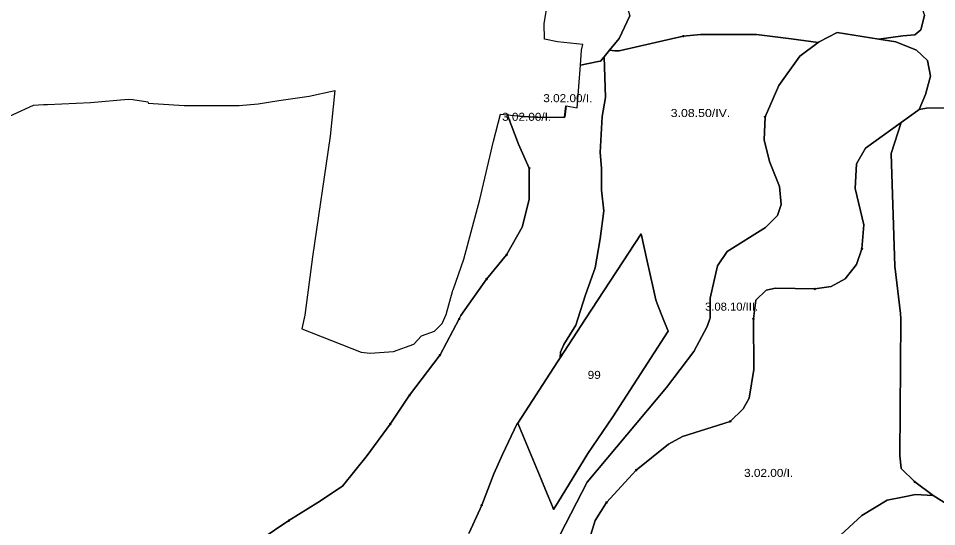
# Model space of a CAD drawing. Extents: x -650455 to -642254, y -1075222 to -1066610.
# Drawn here: x -646541 to -645394, y -1068260 to -1067624 of the extents above; entities that cross this region are included whole.
import ezdxf
from ezdxf.enums import TextEntityAlignment as Align

# ---------------------------------------------------------------- set-up
doc = ezdxf.new("R2010")
doc.units = 0
doc.header["$LTSCALE"] = 4
doc.header["$PDMODE"] = 32
doc.header["$PDSIZE"] = 2
for name, color, linetype, lineweight in [('1', 7, 'Continuous', 25), ('11', 7, 'Continuous', 13), ('12', 7, 'Continuous', 13), ('13', 7, 'Continuous', 13), ('14', 7, 'Continuous', 13)]:
    doc.layers.add(name, color=color, linetype=linetype, lineweight=lineweight)
doc.layers.add('2', color=7, linetype='Continuous')

msp = doc.modelspace()

# ---------------------------------------------------------------- linework, layer by layer
at = {"layer": '1'}
for points in [[(-645802.687, -1067663.876), (-645809.375, -1067672.25), (-645814.125, -1067677.751), (-645816.835, -1067678.312), (-645839.087, -1067682.923), (-645837.619, -1067663.994), (-645836.027, -1067656.984), (-645867.933, -1067653.635), (-645883.859, -1067650.419), (-645884.5, -1067630.76), (-645873.323, -1067563.051), (-645890.073, -1067549.417), (-645890.669, -1067543.411), (-645885.177, -1067516.651), (-645845.49, -1067511.661), (-645830.352, -1067509.283), (-645829.312, -1067510.75), (-645814.25, -1067527.251), (-645796.188, -1067560.375), (-645788.625, -1067583), (-645788.254, -1067585.104), (-645788.25, -1067585.125), (-645777.5, -1067621.251), (-645790.813, -1067649.501)], [(-645857.007, -1067733.671), (-645858.438, -1067747.75), (-645858.794, -1067747.75), (-645857.238, -1067733.631)], [(-645892.381, -1067747.75), (-645895.062, -1067747.75), (-645912.313, -1067746.751), (-645917.164, -1067746.206)], [(-645917.313, -1068130.126), (-645867.687, -1068053.501), (-645864.5, -1068048.626), (-645832.678, -1068000), (-645763.063, -1067893.626), (-645755.688, -1067927.876), (-645748.438, -1067961.001), (-645744.938, -1067976.25), (-645742.687, -1067982.125), (-645735.605, -1068000), (-645729.568, -1068015.238), (-645729.57, -1068015.25), (-645798.69, -1068122.171), (-645829.66, -1068168.341), (-645867.779, -1068230.191), (-645872.671, -1068238), (-645874.15, -1068234.441), (-645882.74, -1068213.72), (-645888.25, -1068200.251)]]:
    msp.add_lwpolyline(points, close=True, dxfattribs=at)
for points in [[(-645416.812, -1067598), (-645409.312, -1067620.625), (-645413.813, -1067638.626), (-645421.375, -1067644.751), (-645436.375, -1067646.251), (-645466.563, -1067650.126)], [(-645466.563, -1067650.126), (-645518.5, -1067642.001), (-645541, -1067653.501), (-645542.25, -1067654.375), (-645576, -1067649.875), (-645619.125, -1067644.625), (-645689.063, -1067644.625), (-645710.625, -1067646.5), (-645790.875, -1067664.75), (-645796.062, -1067664.75), (-645802.687, -1067663.876), (-645790.813, -1067649.501), (-645777.5, -1067621.251)], [(-645149.54, -1067732.723), (-645175, -1067727.5), (-645192.189, -1067725.08), (-645192.187, -1067725.126), (-645210.5, -1067722.501), (-645305, -1067735.501), (-645407, -1067736.5), (-645416, -1067738.001), (-645408, -1067719.5), (-645402, -1067696.5), (-645405.5, -1067677.001), (-645419.5, -1067664), (-645445, -1067653.501), (-645466.563, -1067650.126), (-645436.375, -1067646.251), (-645421.375, -1067644.751), (-645413.813, -1067638.626), (-645409.312, -1067620.625)], [(-645864.5, -1068269.501), (-645830.5, -1068204.001), (-645731.5, -1068085.5), (-645697.5, -1068040.5), (-645681, -1068009.501), (-645677.381, -1068000), (-645677, -1067999), (-645677, -1067974.001), (-645668, -1067933.501), (-645656, -1067915.5), (-645608, -1067885.5), (-645593, -1067870.5), (-645588.5, -1067857.001), (-645590.5, -1067834.5), (-645603, -1067803.001), (-645609.5, -1067776.001), (-645608.5, -1067747.501), (-645591.5, -1067708), (-645565, -1067671.5), (-645542.25, -1067654.375), (-645541, -1067653.501), (-645518.5, -1067642.001), (-645466.563, -1067650.126)], [(-645814.437, -1067791.875), (-645812.125, -1067746.751), (-645807.625, -1067723.125), (-645809.375, -1067672.25), (-645802.687, -1067663.876), (-645796.062, -1067664.75), (-645790.875, -1067664.75), (-645710.625, -1067646.5), (-645689.063, -1067644.625), (-645619.125, -1067644.625), (-645576, -1067649.875), (-645542.25, -1067654.375)], [(-645542.25, -1067654.375), (-645565, -1067671.5), (-645591.5, -1067708), (-645608.5, -1067747.501), (-645609.5, -1067776.001), (-645603, -1067803.001), (-645590.5, -1067834.5), (-645588.5, -1067857.001), (-645593, -1067870.5), (-645608, -1067885.5), (-645656, -1067915.5), (-645668, -1067933.501), (-645677, -1067974.001), (-645677, -1067999), (-645677.381, -1068000), (-645681, -1068009.501), (-645697.5, -1068040.5), (-645731.5, -1068085.5), (-645830.5, -1068204.001), (-645864.5, -1068269.501)], [(-645466.563, -1067650.126), (-645445, -1067653.501), (-645419.5, -1067664), (-645405.5, -1067677.001), (-645402, -1067696.5), (-645408, -1067719.5), (-645416, -1067738.001), (-645417.864, -1067739.367), (-645417.875, -1067739.375), (-645438.5, -1067754.501), (-645483, -1067786.501), (-645494.5, -1067806), (-645496, -1067837), (-645485, -1067882.5), (-645487.5, -1067912.501), (-645494.5, -1067932), (-645508.5, -1067950.001), (-645526, -1067959.5), (-645546.5, -1067962.5), (-645595.5, -1067961.501), (-645607, -1067964), (-645620, -1067976.5), (-645623, -1068000), (-645622.5, -1068063.001), (-645628.5, -1068099.001), (-645636, -1068112.5), (-645652, -1068128.001), (-645711.5, -1068147.001), (-645729, -1068156.501), (-645769.5, -1068189.001), (-645806.5, -1068229.501), (-645820.5, -1068252.001), (-645833, -1068292.501)], [(-645858.438, -1067747.75), (-645857.007, -1067733.671), (-645843.207, -1067736.051), (-645839.087, -1067682.923), (-645816.835, -1067678.312), (-645814.125, -1067677.751), (-645809.375, -1067672.25), (-645807.625, -1067723.125), (-645812.125, -1067746.751), (-645814.437, -1067791.875), (-645812.938, -1067811.625), (-645812.938, -1067839.001), (-645809.875, -1067864.875), (-645814.437, -1067899.875), (-645820.5, -1067936.251), (-645832.688, -1067969.751), (-645842.34, -1068000), (-645844.812, -1068007.75), (-645860, -1068032), (-645863.813, -1068041.625), (-645864.5, -1068048.626)], [(-646334.1, -1067733.4), (-646265.3, -1067733), (-646241.8, -1067731.001), (-646215.6, -1067727.001), (-646177.7, -1067721.601), (-646147.4, -1067714.8), (-646145.864, -1067714.305), (-646151.5, -1067771.46), (-646173.854, -1067922.41), (-646183.168, -1067995.4), (-646186.894, -1068012.483), (-646113.002, -1068041.368), (-646101.826, -1068042.921), (-646072.642, -1068040.746), (-646047.184, -1068031.428), (-646037.588, -1068021.117), (-646021.3, -1068015.101), (-646011.9, -1068005.551), (-646007, -1067994.3), (-645998.8, -1067965.701), (-645998.424, -1067963.832), (-645998.13, -1067963.409), (-645984.78, -1067925.205), (-645964.91, -1067850.661), (-645947.524, -1067777.671), (-645939.12, -1067744.039), (-645930.106, -1067744.937), (-645930.062, -1067745.376), (-645916.5, -1067781.5), (-645902.938, -1067811.625), (-645902.938, -1067850.75), (-645912, -1067885.375), (-645931.312, -1067920.001), (-645956.375, -1067950.25), (-645988.312, -1067995.75), (-645990.562, -1068000), (-646014.375, -1068045), (-646052.625, -1068095.375), (-646076.688, -1068131.501), (-646105.312, -1068170.75)], [(-646573.28, -1067755.921), (-646522.089, -1067732.688), (-646509.898, -1067731.813), (-646504.716, -1067732.104), (-646450.811, -1067729.365), (-646404.167, -1067725.184), (-646398.3, -1067725.601), (-646379.3, -1067728.5), (-646379.05, -1067730.4), (-646334.1, -1067733.4)], [(-645369.687, -1068238.75), (-645398.687, -1068220.501), (-645421.625, -1068203.625), (-645438.375, -1068186.876), (-645438.625, -1068186.5), (-645440, -1068171.001), (-645439, -1068001.001), (-645439.063, -1068000), (-645439.5, -1067993.001), (-645446.5, -1067934), (-645451, -1067793), (-645438.5, -1067754.501), (-645417.875, -1067739.375), (-645417.864, -1067739.367), (-645416, -1067738.001), (-645407, -1067736.5), (-645305, -1067735.501)], [(-646239.25, -1068276.126), (-646203.125, -1068252.001), (-646167, -1068229.375), (-646136.312, -1068209.001), (-646105.312, -1068170.75), (-646076.688, -1068131.501), (-646052.625, -1068095.375), (-646014.375, -1068045), (-645990.562, -1068000), (-645988.312, -1067995.75), (-645956.375, -1067950.25), (-645931.312, -1067920.001), (-645912, -1067885.375), (-645902.938, -1067850.75), (-645902.938, -1067811.625), (-645916.5, -1067781.5), (-645930.062, -1067745.376), (-645930.106, -1067744.937), (-645917.73, -1067746.171), (-645917.164, -1067746.206), (-645912.313, -1067746.751), (-645895.062, -1067747.75), (-645892.381, -1067747.75), (-645892.22, -1067747.761), (-645858.82, -1067747.99), (-645858.794, -1067747.75), (-645858.438, -1067747.75)], [(-645494.5, -1067806), (-645483, -1067786.501), (-645438.5, -1067754.501), (-645451, -1067793), (-645446.5, -1067934), (-645439.5, -1067993.001), (-645439.063, -1068000), (-645439, -1068001.001), (-645440, -1068171.001), (-645438.625, -1068186.5), (-645438.375, -1068186.876), (-645421.625, -1068203.625), (-645398.687, -1068220.501)], [(-645977.937, -1068267.25), (-645962.438, -1068232.625), (-645947.25, -1068193.626), (-645936.625, -1068169.376), (-645918.062, -1068130.501), (-645917.313, -1068130.126), (-645888.25, -1068200.251), (-645882.74, -1068213.72), (-645874.15, -1068234.441), (-645872.671, -1068238), (-645867.779, -1068230.191), (-645829.66, -1068168.341), (-645798.69, -1068122.171), (-645729.57, -1068015.25), (-645729.568, -1068015.238), (-645735.605, -1068000), (-645742.687, -1067982.125), (-645744.938, -1067976.25), (-645748.438, -1067961.001), (-645755.688, -1067927.876), (-645763.063, -1067893.626), (-645832.678, -1068000), (-645864.5, -1068048.626), (-645863.813, -1068041.625), (-645860, -1068032), (-645844.812, -1068007.75), (-645842.34, -1068000), (-645832.688, -1067969.751), (-645820.5, -1067936.251), (-645814.437, -1067899.875), (-645809.875, -1067864.875), (-645812.938, -1067839.001), (-645812.938, -1067811.625), (-645814.437, -1067791.875)], [(-645833, -1068292.501), (-645820.5, -1068252.001), (-645806.5, -1068229.501), (-645769.5, -1068189.001), (-645729, -1068156.501), (-645711.5, -1068147.001), (-645652, -1068128.001), (-645636, -1068112.5), (-645628.5, -1068099.001), (-645622.5, -1068063.001), (-645623, -1068000), (-645620, -1067976.5), (-645607, -1067964), (-645595.5, -1067961.501), (-645546.5, -1067962.5), (-645526, -1067959.5), (-645508.5, -1067950.001), (-645494.5, -1067932), (-645487.5, -1067912.501), (-645485, -1067882.5), (-645496, -1067837), (-645494.5, -1067806)], [(-645864.5, -1068048.626), (-645867.687, -1068053.501), (-645917.313, -1068130.126), (-645918.062, -1068130.501), (-645936.625, -1068169.376), (-645947.25, -1068193.626), (-645962.438, -1068232.625), (-645977.937, -1068267.25)], [(-646105.312, -1068170.75), (-646136.312, -1068209.001), (-646167, -1068229.375), (-646203.125, -1068252.001), (-646239.25, -1068276.126)], [(-645546, -1068299.5), (-645487.5, -1068245.501), (-645456, -1068226.5), (-645434.909, -1068222.163), (-645420.75, -1068219.25), (-645398.687, -1068220.501), (-645369.687, -1068238.75)], [(-645398.687, -1068220.501), (-645420.75, -1068219.25), (-645434.909, -1068222.163), (-645456, -1068226.5), (-645487.5, -1068245.501), (-645546, -1068299.5)]]:
    msp.add_lwpolyline(points, dxfattribs=at)
at = {"layer": '11'}
for p, q in [((-646014.375, -1068045), (-645990.562, -1068000)), ((-646052.625, -1068095.375), (-646014.375, -1068045))]:
    msp.add_line(p, q, dxfattribs=at)
for points in [[(-645884.5, -1067630.76), (-645883.859, -1067650.419), (-645867.933, -1067653.635), (-645836.027, -1067656.984), (-645837.619, -1067663.994), (-645839.087, -1067682.923), (-645816.835, -1067678.312), (-645814.125, -1067677.751), (-645809.375, -1067672.25), (-645802.687, -1067663.876), (-645790.813, -1067649.501), (-645777.5, -1067621.251), (-645788.25, -1067585.125), (-645788.254, -1067585.104), (-645788.625, -1067583), (-645796.188, -1067560.375), (-645814.25, -1067527.251), (-645829.312, -1067510.75), (-645830.352, -1067509.283), (-645845.49, -1067511.661), (-645885.177, -1067516.651), (-645890.669, -1067543.411), (-645890.073, -1067549.417), (-645873.323, -1067563.051)], [(-645858.794, -1067747.75), (-645858.438, -1067747.75), (-645857.007, -1067733.671), (-645857.238, -1067733.631)], [(-645895.062, -1067747.75), (-645892.381, -1067747.75), (-645917.164, -1067746.206), (-645912.313, -1067746.751)]]:
    msp.add_lwpolyline(points, close=True, dxfattribs=at)
for points in [[(-645409.312, -1067620.625), (-645413.813, -1067638.626), (-645421.375, -1067644.751), (-645436.375, -1067646.251), (-645466.563, -1067650.126), (-645445, -1067653.501), (-645419.5, -1067664), (-645405.5, -1067677.001), (-645402, -1067696.5), (-645408, -1067719.5), (-645416, -1067738.001), (-645407, -1067736.5), (-645305, -1067735.501)], [(-645931.312, -1067920.001), (-645912, -1067885.375), (-645902.938, -1067850.75), (-645902.938, -1067811.625), (-645916.5, -1067781.5), (-645930.062, -1067745.376), (-645930.106, -1067744.937), (-645939.12, -1067744.039), (-645947.524, -1067777.671), (-645964.91, -1067850.661), (-645984.78, -1067925.205), (-645998.13, -1067963.409), (-645998.424, -1067963.832), (-645998.8, -1067965.701), (-646007, -1067994.3), (-646011.9, -1068005.551), (-646021.3, -1068015.101), (-646037.588, -1068021.117), (-646047.184, -1068031.428), (-646072.642, -1068040.746), (-646101.826, -1068042.921), (-646113.002, -1068041.368), (-646186.894, -1068012.483), (-646183.168, -1067995.4), (-646173.854, -1067922.41), (-646151.5, -1067771.46), (-646145.864, -1067714.305), (-646147.4, -1067714.8), (-646177.7, -1067721.601), (-646215.6, -1067727.001), (-646241.8, -1067731.001), (-646265.3, -1067733), (-646334.1, -1067733.4), (-646379.05, -1067730.4), (-646379.3, -1067728.5), (-646398.3, -1067725.601), (-646404.167, -1067725.184), (-646450.811, -1067729.365), (-646504.716, -1067732.104), (-646509.898, -1067731.813)], [(-646509.898, -1067731.813), (-646522.089, -1067732.688), (-646573.28, -1067755.921)], [(-645305, -1067735.501), (-645407, -1067736.5), (-645416, -1067738.001), (-645417.864, -1067739.367), (-645417.875, -1067739.375), (-645438.5, -1067754.501), (-645451, -1067793), (-645446.5, -1067934), (-645439.5, -1067993.001), (-645439.063, -1068000), (-645439, -1068001.001), (-645440, -1068171.001), (-645438.625, -1068186.5), (-645438.375, -1068186.876), (-645421.625, -1068203.625), (-645398.687, -1068220.501), (-645369.687, -1068238.75)], [(-645421.625, -1068203.625), (-645438.375, -1068186.876), (-645438.625, -1068186.5), (-645440, -1068171.001), (-645439, -1068001.001), (-645439.063, -1068000), (-645439.5, -1067993.001), (-645446.5, -1067934), (-645451, -1067793), (-645438.5, -1067754.501), (-645483, -1067786.501), (-645494.5, -1067806), (-645496, -1067837), (-645485, -1067882.5), (-645487.5, -1067912.501)], [(-645990.562, -1068000), (-645988.312, -1067995.75), (-645956.375, -1067950.25), (-645931.312, -1067920.001)], [(-645487.5, -1067912.501), (-645494.5, -1067932), (-645508.5, -1067950.001), (-645526, -1067959.5), (-645546.5, -1067962.5)], [(-645546.5, -1067962.5), (-645595.5, -1067961.501), (-645607, -1067964), (-645620, -1067976.5), (-645623, -1068000)], [(-645623, -1068000), (-645622.5, -1068063.001), (-645628.5, -1068099.001), (-645636, -1068112.5), (-645652, -1068128.001)], [(-646268.75, -1068288.751), (-646239.25, -1068276.126), (-646203.125, -1068252.001), (-646167, -1068229.375), (-646136.312, -1068209.001), (-646105.312, -1068170.75), (-646076.688, -1068131.501), (-646052.625, -1068095.375)], [(-645652, -1068128.001), (-645711.5, -1068147.001), (-645729, -1068156.501), (-645769.5, -1068189.001), (-645806.5, -1068229.501)], [(-645791.5, -1068490.5), (-645783, -1068502.5), (-645771, -1068497), (-645757, -1068486), (-645754.063, -1068483.625), (-645712.527, -1068450.515), (-645712.513, -1068450.504), (-645692.438, -1068434.501), (-645613.5, -1068371.5), (-645546, -1068299.5), (-645487.5, -1068245.501), (-645456, -1068226.5), (-645434.909, -1068222.163), (-645420.75, -1068219.25), (-645398.687, -1068220.501), (-645421.625, -1068203.625)], [(-645369.687, -1068238.75), (-645398.687, -1068220.501), (-645420.75, -1068219.25), (-645434.909, -1068222.163), (-645456, -1068226.5), (-645487.5, -1068245.501), (-645546, -1068299.5), (-645613.5, -1068371.5), (-645692.438, -1068434.501), (-645679.625, -1068440.376), (-645667.438, -1068452.5), (-645655.188, -1068466.25), (-645649.125, -1068478.5), (-645644.5, -1068490.751), (-645644.5, -1068501.376), (-645645.161, -1068503.178), (-645645.187, -1068503.251), (-645699.562, -1068559), (-645699.65, -1068559.035), (-645702.75, -1068560.251), (-645735.75, -1068562.626), (-645755.437, -1068561.125), (-645763.25, -1068558.626)], [(-645806.5, -1068229.501), (-645820.5, -1068252.001), (-645833, -1068292.501), (-645837, -1068328.5), (-645828.5, -1068378.001)]]:
    msp.add_lwpolyline(points, dxfattribs=at)
for p in [(-645931.312, -1067920.001), (-645487.5, -1067912.501), (-645546.5, -1067962.5), (-645990.562, -1068000), (-645623, -1068000), (-646014.375, -1068045), (-646052.625, -1068095.375), (-645652, -1068128.001), (-645421.625, -1068203.625), (-645806.5, -1068229.501)]:
    msp.add_point(p, dxfattribs=at)
at = {"layer": '12'}
msp.add_line((-645977.937, -1068267.25), (-645962.438, -1068232.625), dxfattribs=at)
for points in [[(-645755.688, -1067444.626), (-645751.066, -1067481.89), (-645749.67, -1067492.54), (-645786.52, -1067502.401), (-645830.352, -1067509.283), (-645829.312, -1067510.75), (-645814.25, -1067527.251), (-645796.188, -1067560.375), (-645788.625, -1067583), (-645788.254, -1067585.104), (-645788.25, -1067585.125), (-645777.5, -1067621.251), (-645790.813, -1067649.501), (-645802.687, -1067663.876), (-645796.062, -1067664.75), (-645790.875, -1067664.75), (-645710.625, -1067646.5)], [(-645710.625, -1067646.5), (-645689.063, -1067644.625), (-645619.125, -1067644.625), (-645576, -1067649.875), (-645542.25, -1067654.375), (-645541, -1067653.501), (-645518.5, -1067642.001), (-645466.563, -1067650.126), (-645436.375, -1067646.251), (-645421.375, -1067644.751), (-645413.813, -1067638.626), (-645409.312, -1067620.625)], [(-645962.438, -1068232.625), (-645947.25, -1068193.626), (-645936.625, -1068169.376), (-645918.062, -1068130.501), (-645917.313, -1068130.126), (-645867.687, -1068053.501), (-645864.5, -1068048.626), (-645863.813, -1068041.625), (-645860, -1068032), (-645844.812, -1068007.75), (-645842.34, -1068000), (-645832.688, -1067969.751), (-645820.5, -1067936.251), (-645814.437, -1067899.875), (-645809.875, -1067864.875), (-645812.938, -1067839.001), (-645812.938, -1067811.625), (-645814.437, -1067791.875), (-645812.125, -1067746.751), (-645807.625, -1067723.125), (-645809.375, -1067672.25), (-645814.125, -1067677.751), (-645816.835, -1067678.312), (-645839.087, -1067682.923), (-645843.207, -1067736.051), (-645857.007, -1067733.671), (-645858.438, -1067747.75), (-645858.794, -1067747.75), (-645858.82, -1067747.99), (-645892.22, -1067747.761), (-645892.381, -1067747.75), (-645895.062, -1067747.75), (-645912.313, -1067746.751), (-645917.164, -1067746.206), (-645917.73, -1067746.171), (-645930.106, -1067744.937)], [(-645930.106, -1067744.937), (-645930.062, -1067745.376), (-645916.5, -1067781.5), (-645902.938, -1067811.625)], [(-645902.938, -1067811.625), (-645902.938, -1067850.75), (-645912, -1067885.375), (-645931.312, -1067920.001), (-645956.375, -1067950.25)], [(-645956.375, -1067950.25), (-645988.312, -1067995.75), (-645990.562, -1068000), (-646014.375, -1068045)], [(-646014.375, -1068045), (-646052.625, -1068095.375), (-646076.688, -1068131.501)], [(-646076.688, -1068131.501), (-646105.312, -1068170.75), (-646136.312, -1068209.001), (-646167, -1068229.375), (-646203.125, -1068252.001)], [(-646203.125, -1068252.001), (-646239.25, -1068276.126), (-646268.75, -1068288.751), (-646305.5, -1068298.626)]]:
    msp.add_lwpolyline(points, dxfattribs=at)
for p in [(-645710.625, -1067646.5), (-645930.106, -1067744.937), (-645902.938, -1067811.625), (-645956.375, -1067950.25), (-646014.375, -1068045), (-646076.688, -1068131.501), (-645962.438, -1068232.625), (-646203.125, -1068252.001)]:
    msp.add_point(p, dxfattribs=at)
at = {"layer": '13'}
for points in [[(-645769.5, -1068189.001), (-645729, -1068156.501), (-645711.5, -1068147.001), (-645652, -1068128.001), (-645636, -1068112.5), (-645628.5, -1068099.001), (-645622.5, -1068063.001), (-645623, -1068000), (-645620, -1067976.5), (-645607, -1067964), (-645595.5, -1067961.501), (-645546.5, -1067962.5), (-645526, -1067959.5), (-645508.5, -1067950.001), (-645494.5, -1067932), (-645487.5, -1067912.501), (-645485, -1067882.5), (-645496, -1067837), (-645494.5, -1067806), (-645483, -1067786.501), (-645438.5, -1067754.501), (-645417.875, -1067739.375), (-645417.864, -1067739.368), (-645416, -1067738.001), (-645408, -1067719.5), (-645402, -1067696.5), (-645405.5, -1067677.001), (-645419.5, -1067664), (-645445, -1067653.501), (-645466.563, -1067650.126), (-645518.5, -1067642.001), (-645541, -1067653.501), (-645542.25, -1067654.375), (-645565, -1067671.5), (-645591.5, -1067708), (-645608.5, -1067747.501), (-645609.5, -1067776.001), (-645603, -1067803.001), (-645590.5, -1067834.5), (-645588.5, -1067857.001)], [(-645588.5, -1067857.001), (-645593, -1067870.5), (-645608, -1067885.5), (-645656, -1067915.5), (-645668, -1067933.501), (-645677, -1067974.001)], [(-645677, -1067974.001), (-645677, -1067999), (-645677.381, -1068000), (-645681, -1068009.501), (-645697.5, -1068040.5), (-645731.5, -1068085.5), (-645830.5, -1068204.001), (-645864.5, -1068269.501), (-645883, -1068323.5), (-645887, -1068364), (-645883, -1068395.001), (-645873, -1068422.501), (-645858, -1068454), (-645844, -1068521.5)], [(-645791.5, -1068490.5), (-645800.5, -1068459.001), (-645828.5, -1068378.001), (-645837, -1068328.5), (-645833, -1068292.501), (-645820.5, -1068252.001), (-645806.5, -1068229.501), (-645769.5, -1068189.001)]]:
    msp.add_lwpolyline(points, dxfattribs=at)
msp.add_point((-645769.5, -1068189.001), dxfattribs=at)
at = {"layer": '14'}
for points in [[(-645608.5, -1067747.501), (-645591.5, -1067708), (-645565, -1067671.5), (-645542.25, -1067654.375), (-645576, -1067649.875), (-645619.125, -1067644.625), (-645689.063, -1067644.625), (-645710.625, -1067646.5), (-645790.875, -1067664.75), (-645796.062, -1067664.75), (-645802.687, -1067663.876), (-645809.375, -1067672.25), (-645807.625, -1067723.125), (-645812.125, -1067746.751), (-645814.437, -1067791.875), (-645812.938, -1067811.625), (-645812.938, -1067839.001), (-645809.875, -1067864.875), (-645814.437, -1067899.875), (-645820.5, -1067936.251), (-645832.688, -1067969.751), (-645842.34, -1068000), (-645844.812, -1068007.75), (-645860, -1068032), (-645863.813, -1068041.625), (-645864.5, -1068048.626), (-645832.678, -1068000), (-645763.063, -1067893.626), (-645755.688, -1067927.876), (-645748.438, -1067961.001), (-645744.938, -1067976.25), (-645742.687, -1067982.125), (-645735.605, -1068000)], [(-645873, -1068422.501), (-645883, -1068395.001), (-645887, -1068364), (-645883, -1068323.5), (-645864.5, -1068269.501), (-645830.5, -1068204.001), (-645731.5, -1068085.5), (-645697.5, -1068040.5), (-645681, -1068009.501), (-645677.381, -1068000), (-645677, -1067999), (-645677, -1067974.001), (-645668, -1067933.501), (-645656, -1067915.5), (-645608, -1067885.5), (-645593, -1067870.5), (-645588.5, -1067857.001), (-645590.5, -1067834.5), (-645603, -1067803.001), (-645609.5, -1067776.001), (-645608.5, -1067747.501)], [(-645735.605, -1068000), (-645729.568, -1068015.238), (-645729.57, -1068015.25), (-645798.69, -1068122.171), (-645829.66, -1068168.341), (-645867.779, -1068230.191), (-645872.671, -1068238), (-645874.15, -1068234.441), (-645882.74, -1068213.72), (-645888.25, -1068200.251), (-645917.313, -1068130.126), (-645918.062, -1068130.501), (-645936.625, -1068169.376), (-645947.25, -1068193.626), (-645962.438, -1068232.625), (-645977.937, -1068267.25), (-645985.875, -1068285.501), (-645985.9, -1068285.558), (-645993.125, -1068302.125), (-646002.938, -1068334.001), (-646001.687, -1068364.75), (-645989.375, -1068400.25), (-645977.063, -1068439.625)]]:
    msp.add_lwpolyline(points, dxfattribs=at)
msp.add_point((-645608.5, -1067747.501), dxfattribs=at)

# ---------------------------------------------------------------- texts
at = {"layer": '2'}
for s, width, p in [('3.02.00/I.', 1.1, (-645854.845, -1067729.045)), ('3.08.50/IV.', 1.15, (-645689.144, -1067747.618)), ('3.02.00/I.', 1.1, (-645906.285, -1067752.331)), ('3.08.10/III.', 1.05, (-645650.302, -1067989.624)), ('99', 1.1, (-645821.872, -1068074.921)), ('3.02.00/I.', 1.1, (-645604.029, -1068197.454))]:
    msp.add_text(s, height=10, dxfattribs=dict(at, width=width)).set_placement(p, align=Align.CENTER)

doc.saveas('drawing.dxf')
